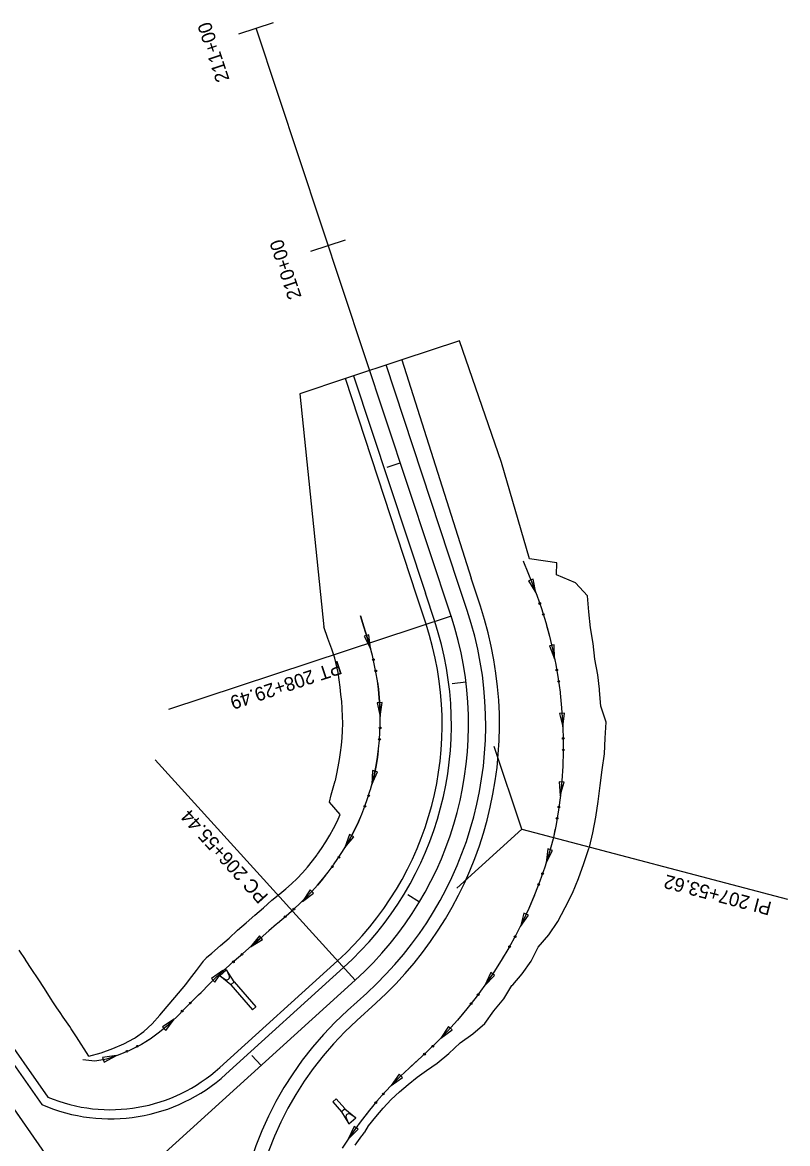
# Model space of a CAD drawing. Extents: x 916431 to 921570, y 1763982 to 1768032.
# Drawn here: x 919470.1 to 919804.2, y 1764528.2 to 1765017.9 of the extents above; entities that cross this region are included whole.
import ezdxf

# ---------------------------------------------------------------- set-up
doc = ezdxf.new("R2010")
doc.units = 0
for name, color, linetype in [('43', 7, 'Continuous'), ('R_Drainage', 7, 'Continuous'), ('R_Horz Alg', 7, 'Continuous'), ('R_Horz Alg Annot', 7, 'Continuous'), ('R_Horz Alg Stationing', 7, 'Continuous'), ('R_Proposed Const Limits', 7, 'Continuous'), ('R_Proposed Road', 7, 'Continuous'), ('R_Shld', 7, 'Continuous'), ('R_Special Ditch', 7, 'Continuous')]:
    doc.layers.add(name, color=color, linetype=linetype)

# ---------------------------------------------------------------- blocks, each defined once
blk = doc.blocks.new('24F_PL')
at = {"layer": '43'}
for p, q in [((0, 0), (-0.1, -0.612)), ((0, 0), (0.2, 0)), ((0.2, 0), (0.3, -0.612)), ((-0.1, -0.612), (-0.011, -0.332)), ((0.3, -0.612), (0.211, -0.332)), ((-0.1, -0.612), (0.3, -0.612))]:
    blk.add_line(p, q, dxfattribs=at)
blk.add_arc((0.1, -0.367), 0.117, 17.5299, 162.4701, dxfattribs=at)

msp = doc.modelspace()

# ---------------------------------------------------------------- linework, layer by layer
at = {"layer": 'R_Drainage'}
for p, q in [((919561.02, 1764597.49), (919570.54, 1764586.58)), ((919562.53, 1764598.8), (919572.05, 1764587.9)), ((919570.54, 1764586.58), (919572.05, 1764587.9)), ((919605.59, 1764546.42), (919607.09, 1764547.73)), ((919607.09, 1764547.73), (919610.86, 1764543.42)), ((919605.59, 1764546.42), (919609.35, 1764542.1)), ((919609.35, 1764542.1), (919610.86, 1764543.42))]:
    msp.add_line(p, q, dxfattribs=at)
at = {"layer": 'R_Horz Alg'}
for p, q in [((919657.22, 1764758.63), (919572.12, 1765015.41)), ((919553.63, 1764418.82), (919407.55, 1764627.45)), ((919500.23, 1764495.09), (919615.38, 1764599.5))]:
    msp.add_line(p, q, dxfattribs=at)
msp.add_arc((919514.1, 1764711.2), 150.78, 312.1986, 18.3372, dxfattribs=at)
at = {"layer": 'R_Horz Alg Annot'}
for q in [(919676.1, 1764701.68), (919659.83, 1764639.8)]:
    msp.add_line((919688.11, 1764665.44), q, dxfattribs=at)
for points in [[(919657.22, 1764758.63), (919533.82, 1764717.73)], [(919615.38, 1764599.5), (919528.06, 1764695.8)], [(919688.11, 1764665.44), (919804.17, 1764634.93)]]:
    msp.add_lwpolyline(points, dxfattribs=at)
at = {"layer": 'R_Horz Alg Stationing'}
for points in [[(919564.52, 1765012.89), (919579.71, 1765017.92)], [(919564.52, 1765012.89), (919579.71, 1765017.92)], [(919595.99, 1764917.97), (919611.17, 1764923)], [(919629.34, 1764823.68), (919635.04, 1764825.56)], [(919657.76, 1764729.17), (919663.71, 1764729.92)], [(919638.37, 1764636.92), (919643.52, 1764633.84)], [(919570.28, 1764566.7), (919574.31, 1764562.26)]]:
    msp.add_lwpolyline(points, dxfattribs=at)
at = {"layer": 'R_Proposed Const Limits'}
for points in [[(919691.45, 1764783.64), (919679.27, 1764825.71), (919660.97, 1764878.89), (919635.69, 1764870.51)], [(919611.09, 1764862.36), (919591.16, 1764855.75), (919601.71, 1764753.9)], [(919615.36, 1764527.45), (919618.35, 1764531.59), (919618.54, 1764531.85), (919619.28, 1764532.82), (919619.5, 1764533.11), (919619.56, 1764533.19), (919621.24, 1764535.85), (919624.41, 1764539.8), (919627.65, 1764543.67), (919631.03, 1764547.38), (919634.75, 1764550.72), (919638.55, 1764553.97), (919642.44, 1764557.13), (919646.56, 1764560.04), (919651.13, 1764563.24), (919656.34, 1764567.48), (919661.15, 1764572.15), (919666.78, 1764576.13), (919671.94, 1764580.63), (919675.91, 1764586.15), (919680.25, 1764591.38), (919683.8, 1764597.18), (919684.28, 1764597.56), (919688.34, 1764602.33), (919692.29, 1764607.92), (919695.33, 1764614.03), (919699.97, 1764619.35), (919703.81, 1764625.15), (919707.13, 1764631.25), (919710.22, 1764637.49), (919712.85, 1764643.94), (919715.25, 1764650.48), (919717.45, 1764657.1), (919717.62, 1764657.68), (919719.13, 1764663.87), (919720.41, 1764670.73), (919721.47, 1764677.62), (919722.39, 1764684.53), (919723.15, 1764691.45), (919724.25, 1764698.35), (919724.57, 1764705.33), (919724.92, 1764712.31), (919722.61, 1764719.22), (919722.1, 1764726.12), (919722.05, 1764726.71), (919721.34, 1764732.99), (919719.99, 1764739.78), (919719.24, 1764746.64), (919718.08, 1764753.45), (919717.36, 1764760.38), (919716.8, 1764767.42), (919711.61, 1764773.1), (919703.23, 1764776.56), (919703.37, 1764781.87), (919692.48, 1764783.53), (919691.45, 1764783.64)], [(919499.1, 1764566.34), (919504.5, 1764567.84), (919509.57, 1764569.69), (919514.39, 1764571.81), (919519.01, 1764574.16), (919519.52, 1764574.46), (919523.06, 1764577.14), (919526.75, 1764580.51), (919530.14, 1764584.22), (919533.36, 1764588.11), (919536.62, 1764591.96), (919539.88, 1764595.81), (919541.44, 1764597.68), (919543.03, 1764599.78), (919546.1, 1764603.84), (919549.15, 1764607.91), (919549.36, 1764608.15), (919550.15, 1764609.06), (919550.39, 1764609.33), (919550.46, 1764609.41), (919552.75, 1764611.39), (919556.53, 1764614.67), (919560.3, 1764617.95), (919563.98, 1764621.33), (919567.76, 1764624.61), (919571.53, 1764627.89), (919575.31, 1764631.17), (919579.04, 1764634.5), (919582.51, 1764637.33), (919585.09, 1764639.47), (919587.6, 1764641.69), (919590.04, 1764644.01), (919592.4, 1764646.43), (919594.6, 1764648.98), (919596.71, 1764651.62), (919598.73, 1764654.33), (919598.9, 1764654.57), (919600.67, 1764657.11), (919602.52, 1764659.95), (919604.27, 1764662.86), (919605.91, 1764665.83), (919607.46, 1764668.86), (919608.89, 1764671.94), (919604.16, 1764677.35), (919604.89, 1764680.47), (919605.78, 1764683.52), (919606.65, 1764686.58), (919606.72, 1764686.84), (919607.37, 1764689.67), (919607.97, 1764692.78), (919608.47, 1764695.92), (919609.01, 1764699.04), (919609.4, 1764702.19), (919609.68, 1764705.36), (919609.86, 1764708.53), (919609.93, 1764711.7), (919609.9, 1764714.88), (919609.74, 1764718.06), (919609.72, 1764718.33), (919609.5, 1764721.23), (919609.16, 1764724.39), (919608.8, 1764727.56), (919608.39, 1764730.73), (919607.89, 1764733.89), (919607.27, 1764737.04), (919606.55, 1764740.17), (919605.2, 1764744.07), (919603.47, 1764748.76), (919601.71, 1764753.9)], [(919499.1, 1764566.34), (919493.68, 1764574.8), (919491.36, 1764578.29), (919490.73, 1764579.24), (919487.95, 1764583.4), (919486.62, 1764585.36), (919485.13, 1764587.53), (919483.73, 1764589.61), (919482.4, 1764591.72), (919479.71, 1764595.95), (919476.93, 1764600.1), (919474.17, 1764604.27), (919471.45, 1764608.47), (919471.38, 1764608.57), (919468.74, 1764612.68)]]:
    msp.add_lwpolyline(points, dxfattribs=at)
at = {"layer": 'R_Proposed Road'}
for p, q in [((919635.69, 1764870.51), (919611.09, 1764862.36)), ((919660.26, 1764773.31), (919628.96, 1764868.28)), ((919614.7, 1764863.55), (919646.02, 1764768.59)), ((919664.34, 1764760.99), (919660.26, 1764773.31)), ((919650.1, 1764756.27), (919646.02, 1764768.59)), ((919416.56, 1764633.76), (919478.54, 1764545.24)), ((919610.34, 1764605.05), (919558.91, 1764558.42)), ((919620.42, 1764593.94), (919612.01, 1764586.31))]:
    msp.add_line(p, q, dxfattribs=at)
for centre, radius, start, end in [((919514.1, 1764711.2), 158.28, 312.1986, 18.3372), ((919514.1, 1764711.2), 143.28, 312.1986, 18.3372), ((919712.76, 1764475.19), 150, 132.1986, 219.2888), ((919508.53, 1764613.98), 75, 246.4231, 312.1986), ((919382.7, 1764382.24), 150, 34.9992, 96.7925)]:
    msp.add_arc(centre, radius, start, end, dxfattribs=at)
at = {"layer": 'R_Shld'}
for p, q in [((919635.69, 1764870.51), (919665.96, 1764775.19)), ((919642.23, 1764767.33), (919611.09, 1764862.36)), ((919670.04, 1764762.88), (919665.96, 1764775.19)), ((919646.31, 1764755.01), (919642.23, 1764767.33)), ((919419.84, 1764636.05), (919481.16, 1764548.47)), ((919607.66, 1764608.02), (919556.23, 1764561.39)), ((919624.45, 1764589.5), (919616.04, 1764581.87))]:
    msp.add_line(p, q, dxfattribs=at)
for centre, radius, start, end in [((919514.1, 1764711.2), 164.28, 312.1986, 18.3372), ((919514.1, 1764711.2), 139.28, 312.1986, 18.3372), ((919712.76, 1764475.19), 144, 132.1986, 219.2888), ((919508.53, 1764613.98), 71, 247.3197, 312.1986)]:
    msp.add_arc(centre, radius, start, end, dxfattribs=at)
at = {"layer": 'R_Special Ditch'}
for p, q in [((919693.08, 1764774.77), (919691.1, 1764774.01)), ((919691.1, 1764774.01), (919694.25, 1764768.79)), ((919694.25, 1764768.79), (919693.08, 1764774.77)), ((919621.36, 1764750.45), (919619.34, 1764749.84)), ((919619.34, 1764749.84), (919622.1, 1764744.4)), ((919622.1, 1764744.4), (919621.36, 1764750.45)), ((919702.29, 1764746.02), (919700.22, 1764745.6)), ((919700.22, 1764745.6), (919702.46, 1764739.93)), ((919702.46, 1764739.93), (919702.29, 1764746.02)), ((919627.14, 1764720.78), (919625.02, 1764720.7)), ((919625.02, 1764720.7), (919626.3, 1764714.74)), ((919626.3, 1764714.74), (919627.14, 1764720.78)), ((919706.75, 1764716.2), (919704.64, 1764716.06)), ((919704.64, 1764716.06), (919706.11, 1764710.15)), ((919706.11, 1764710.15), (919706.75, 1764716.2)), ((919623, 1764691.09), (919622.67, 1764685.01)), ((919622.67, 1764685.01), (919625.06, 1764690.61)), ((919625.06, 1764690.61), (919623, 1764691.09)), ((919706.59, 1764686.02), (919704.48, 1764686.23)), ((919704.48, 1764686.23), (919704.95, 1764680.15)), ((919704.95, 1764680.15), (919706.59, 1764686.02)), ((919612.93, 1764663.21), (919610.93, 1764657.45)), ((919610.93, 1764657.45), (919614.78, 1764662.18)), ((919614.78, 1764662.18), (919612.93, 1764663.21)), ((919699.53, 1764656.86), (919698.75, 1764650.82)), ((919698.75, 1764650.82), (919701.55, 1764656.23)), ((919701.55, 1764656.23), (919699.53, 1764656.86)), ((919595.73, 1764639.01), (919592.33, 1764633.96)), ((919592.33, 1764633.96), (919597.25, 1764637.55)), ((919597.25, 1764637.55), (919595.73, 1764639.01)), ((919689.08, 1764628.88), (919687.51, 1764623)), ((919687.51, 1764623), (919691, 1764627.99)), ((919691, 1764627.99), (919689.08, 1764628.88)), ((919573.56, 1764618.91), (919569.73, 1764614.17)), ((919569.73, 1764614.17), (919574.95, 1764617.31)), ((919574.95, 1764617.31), (919573.56, 1764618.91)), ((919557.6, 1764603.71), (919552.61, 1764600.22)), ((919554.11, 1764598.72), (919557.6, 1764603.71)), ((919674.54, 1764602.84), (919672.01, 1764597.29)), ((919672.01, 1764597.29), (919676.28, 1764601.64)), ((919676.28, 1764601.64), (919674.54, 1764602.84)), ((919552.61, 1764600.22), (919554.11, 1764598.72)), ((919536.34, 1764582.49), (919531.27, 1764579.11)), ((919532.74, 1764577.58), (919536.34, 1764582.49)), ((919531.27, 1764579.11), (919532.74, 1764577.58)), ((919656.18, 1764579.32), (919652.77, 1764574.26)), ((919652.77, 1764574.26), (919657.7, 1764577.85)), ((919657.7, 1764577.85), (919656.18, 1764579.32)), ((919511.14, 1764566.59), (919505.12, 1764565.7)), ((919505.12, 1764565.7), (919505.78, 1764563.69)), ((919505.78, 1764563.69), (919511.14, 1764566.59)), ((919634.58, 1764558.49), (919631.05, 1764553.53)), ((919631.05, 1764553.53), (919636.07, 1764556.98)), ((919636.07, 1764556.98), (919634.58, 1764558.49)), ((919614.88, 1764535.62), (919612.31, 1764530.1)), ((919612.31, 1764530.1), (919616.62, 1764534.4)), ((919616.62, 1764534.4), (919614.88, 1764535.62))]:
    msp.add_line(p, q, dxfattribs=at)
for points in [[(919688.74, 1764782.74), (919688.9, 1764782.34), (919690.76, 1764777.69), (919692.61, 1764773.04), (919694.64, 1764767.78), (919696.7, 1764761.85), (919698.57, 1764755.83), (919700.24, 1764749.75), (919701.71, 1764743.61), (919702.97, 1764737.41), (919704.03, 1764731.17), (919704.82, 1764725.42), (919704.88, 1764724.88), (919705.53, 1764718.56), (919705.97, 1764712.21), (919706.19, 1764705.84), (919706.2, 1764699.46), (919706, 1764693.07), (919705.59, 1764686.68), (919704.96, 1764680.29), (919704.13, 1764673.93), (919703.07, 1764667.58), (919701.93, 1764661.8), (919701.79, 1764661.27), (919700.07, 1764655.06), (919698.15, 1764648.91), (919696.03, 1764642.83), (919693.7, 1764636.81), (919691.18, 1764630.88), (919688.46, 1764625.04), (919685.54, 1764619.28), (919682.44, 1764613.63), (919679.15, 1764608.07), (919675.98, 1764603.1), (919675.68, 1764602.63), (919672.03, 1764597.31), (919668.2, 1764592.11), (919664.2, 1764587.04), (919660.03, 1764582.1), (919655.71, 1764577.3), (919651.22, 1764572.65), (919646.58, 1764568.15), (919642.57, 1764564.43), (919638.89, 1764561.04), (919635.23, 1764557.64), (919631.66, 1764554.13), (919628.21, 1764550.49), (919624.88, 1764546.73), (919621.66, 1764542.83), (919618.55, 1764538.82), (919616.72, 1764536.32), (919616.66, 1764536.24), (919616.44, 1764535.95), (919615.72, 1764534.96), (919615.53, 1764534.7), (919612.59, 1764530.5), (919609.77, 1764526.17)], [(919688.74, 1764782.74), (919688.9, 1764782.34), (919690.76, 1764777.69), (919692.61, 1764773.04), (919694.25, 1764768.79)], [(919556.56, 1764602.68), (919558.84, 1764604.67), (919562.61, 1764607.96), (919566.38, 1764611.24), (919570.15, 1764614.53), (919573.92, 1764617.82), (919577.69, 1764621.11), (919581.45, 1764624.39), (919585.22, 1764627.68), (919588.67, 1764630.68), (919591.36, 1764633.13), (919593.98, 1764635.67), (919596.51, 1764638.3), (919598.95, 1764641.01), (919601.31, 1764643.8), (919603.57, 1764646.67), (919605.74, 1764649.62), (919605.93, 1764649.88), (919607.83, 1764652.63), (919609.83, 1764655.71), (919611.72, 1764658.86), (919613.51, 1764662.07), (919615.19, 1764665.35), (919616.77, 1764668.68), (919618.23, 1764672.06), (919619.59, 1764675.5), (919620.83, 1764678.98), (919621.95, 1764682.51), (919622.04, 1764682.81), (919622.92, 1764686.08), (919623.76, 1764689.69), (919624.48, 1764693.32), (919625.09, 1764696.98), (919625.57, 1764700.67), (919625.93, 1764704.36), (919626.16, 1764708.07), (919626.28, 1764711.79), (919626.27, 1764715.51), (919626.13, 1764719.23), (919626.12, 1764719.55), (919625.9, 1764722.95), (919625.54, 1764726.67), (919625.06, 1764730.37), (919624.46, 1764734.06), (919623.73, 1764737.73), (919622.89, 1764741.37), (919621.92, 1764744.99), (919620.64, 1764749.19), (919619.16, 1764753.96), (919617.68, 1764758.74)], [(919617.68, 1764758.74), (919619.16, 1764753.96), (919620.64, 1764749.19), (919621.92, 1764744.99), (919622.08, 1764744.4)], [(919698.92, 1764754.54), (919698.93, 1764754.51)], [(919698.93, 1764754.51), (919700.24, 1764749.75), (919701.71, 1764743.61), (919702.46, 1764739.93)], [(919625.15, 1764729.73), (919625.15, 1764729.69)], [(919625.15, 1764729.69), (919625.54, 1764726.67), (919625.9, 1764722.95), (919626.12, 1764719.55), (919626.13, 1764719.23), (919626.27, 1764715.51), (919626.27, 1764714.74)], [(919704.86, 1764725.13), (919704.86, 1764725.09)], [(919704.86, 1764725.09), (919704.88, 1764724.88), (919705.53, 1764718.56), (919705.97, 1764712.21), (919706.04, 1764710.14)], [(919625.45, 1764699.74), (919625.09, 1764696.98), (919624.48, 1764693.32), (919623.76, 1764689.69), (919622.92, 1764686.08), (919622.63, 1764685.02)], [(919625.45, 1764699.78), (919625.45, 1764699.74)], [(919706.07, 1764695.11), (919706, 1764693.07), (919705.59, 1764686.68), (919704.96, 1764680.29), (919704.95, 1764680.15)], [(919706.07, 1764695.15), (919706.07, 1764695.11)], [(919617.7, 1764670.83), (919616.77, 1764668.68), (919615.19, 1764665.35), (919613.51, 1764662.07), (919611.72, 1764658.86), (919610.89, 1764657.48)], [(919617.71, 1764670.86), (919617.7, 1764670.83)], [(919702.62, 1764665.3), (919701.93, 1764661.8), (919701.79, 1764661.27), (919700.07, 1764655.06), (919698.75, 1764650.82)], [(919702.63, 1764665.34), (919702.62, 1764665.3)], [(919602.37, 1764645.14), (919602.35, 1764645.11)], [(919602.35, 1764645.11), (919601.31, 1764643.8), (919598.95, 1764641.01), (919596.51, 1764638.3), (919593.98, 1764635.67), (919592.27, 1764634.02)], [(919693.65, 1764636.68), (919691.18, 1764630.88), (919688.46, 1764625.04), (919687.44, 1764623.03)], [(919693.66, 1764636.72), (919693.65, 1764636.68)], [(919581.03, 1764624.03), (919577.69, 1764621.11), (919573.92, 1764617.82), (919570.15, 1764614.53), (919569.73, 1764614.17)], [(919581.06, 1764624.05), (919581.03, 1764624.03)], [(919680.2, 1764609.85), (919679.15, 1764608.07), (919675.98, 1764603.1), (919675.68, 1764602.63), (919672.03, 1764597.31), (919672.01, 1764597.29)], [(919680.22, 1764609.89), (919680.21, 1764609.85)], [(919496.48, 1764564.95), (919501.72, 1764564.34), (919506.91, 1764565.18), (919512.09, 1764566.9), (919516.98, 1764568.96), (919521.58, 1764571.33), (919522.09, 1764571.62), (919525.92, 1764573.98), (919530.01, 1764576.92), (919533.86, 1764580.12), (919537.47, 1764583.57), (919541.01, 1764587.12), (919544.55, 1764590.66), (919546.26, 1764592.37), (919548.09, 1764594.2), (919551.63, 1764597.74), (919555.17, 1764601.28), (919555.39, 1764601.5), (919556.24, 1764602.35), (919556.49, 1764602.6), (919556.56, 1764602.68)], [(919547, 1764593.1), (919548.09, 1764594.2), (919551.63, 1764597.74), (919555.17, 1764601.28), (919555.39, 1764601.5), (919556.24, 1764602.35), (919556.49, 1764602.6), (919556.56, 1764602.68)], [(919558.4, 1764604.28), (919556.56, 1764602.68)], [(919558.43, 1764604.3), (919558.4, 1764604.28)], [(919546.97, 1764593.08), (919547, 1764593.1)], [(919524.62, 1764573.18), (919525.92, 1764573.98), (919530.01, 1764576.92), (919533.86, 1764580.12), (919536.34, 1764582.49)], [(919662.82, 1764585.4), (919660.03, 1764582.1), (919655.71, 1764577.3), (919652.77, 1764574.26)], [(919662.84, 1764585.43), (919662.82, 1764585.4)], [(919524.59, 1764573.16), (919524.62, 1764573.18)], [(919496.48, 1764564.95), (919501.72, 1764564.34), (919506.91, 1764565.18), (919511.14, 1764566.59)], [(919641.93, 1764563.85), (919638.89, 1764561.04), (919635.23, 1764557.64), (919631.66, 1764554.13), (919631.07, 1764553.5)], [(919641.96, 1764563.87), (919641.93, 1764563.85)], [(919621.17, 1764542.2), (919618.55, 1764538.82), (919616.72, 1764536.32), (919616.66, 1764536.24), (919616.44, 1764535.95), (919615.72, 1764534.96), (919615.53, 1764534.7), (919612.59, 1764530.5), (919612.32, 1764530.09)], [(919621.19, 1764542.23), (919621.17, 1764542.2)]]:
    msp.add_lwpolyline(points, dxfattribs=at)
for centre in [(919695.96, 1764764.09), (919697.52, 1764759.33), (919623.35, 1764739.56), (919624.38, 1764734.65), (919703.41, 1764735.02), (919704.22, 1764730.07), (919626.25, 1764709.74), (919625.99, 1764704.73), (919706.23, 1764705.14), (919706.24, 1764700.13), (919621.26, 1764680.2), (919619.61, 1764675.47), (919704.33, 1764675.19), (919703.55, 1764670.24), (919608.26, 1764653.22), (919605.4, 1764649.1), (919697.2, 1764646.06), (919695.5, 1764641.35), (919588.62, 1764630.59), (919584.84, 1764627.3), (919685.19, 1764618.56), (919565.98, 1764610.85), (919682.78, 1764614.17), (919562.21, 1764607.55), (919669.07, 1764593.24), (919539.88, 1764586.03), (919543.42, 1764589.58), (919666.01, 1764589.27), (919515.77, 1764568.49), (919520.26, 1764570.69), (919645.64, 1764567.23), (919649.26, 1764570.7), (919627.67, 1764549.83), (919624.37, 1764546.06)]:
    msp.add_circle(centre, 0.375, dxfattribs=at)

# ---------------------------------------------------------------- block references
at = {"layer": 'R_Drainage', "yscale": 10}
for p, xscale, rotation in [((919562.53, 1764598.8), 10, -138.89311382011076), ((919609.35, 1764542.1), 10.000000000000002, 41.10688617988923)]:
    msp.add_blockref('24F_PL', p, dxfattribs=dict(at, xscale=xscale, rotation=rotation))

# ---------------------------------------------------------------- texts
at = {"layer": 'R_Horz Alg Annot'}
for s, rotation, p in [('PT 208+29.49', 198.3372, (919608.27, 1764739.25)), ('PC 206+55.44', 132.1986, (919577.81, 1764636.47)), ('PI 207+53.62', 165.2679, (919797.6, 1764633.55))]:
    msp.add_text(s, height=6, rotation=rotation, dxfattribs=at).set_placement(p)
at = {"layer": 'R_Horz Alg Stationing'}
for s, p in [('211+00', (919560.58, 1764993)), ('211+00', (919560.58, 1764993)), ('210+00', (919592.04, 1764898.07))]:
    msp.add_text(s, height=6, rotation=108.3372, dxfattribs=at).set_placement(p)

doc.saveas('drawing.dxf')
